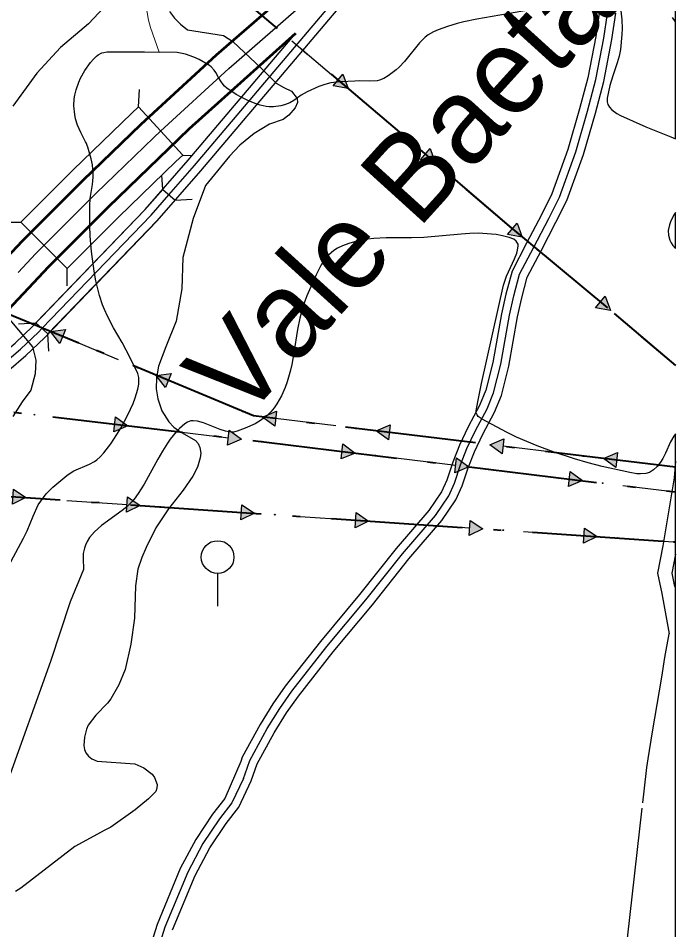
# Model space of a CAD drawing. Extents: x -64005 to -55000, y -89025 to -80000.
# Drawn here: x -55804 to -55000, y -84948 to -83834 of the extents above; entities that cross this region are included whole.
import ezdxf
from ezdxf.enums import TextEntityAlignment as Align

# ---------------------------------------------------------------- set-up
doc = ezdxf.new("R2010")
doc.units = 0
doc.header["$LTSCALE"] = 32
for name, pattern in [('DASH_DOUBLE_DOT', [9.2, 5, -1.2, 0.3, -1.2, 0.3, -1.2]), ('DOT_DASHED', [7.7, 5, -1.2, 0.3, -1.2]), ('LONG_DASHED', [7.5, 6, -1.5])]:
    doc.linetypes.add(name, pattern=pattern)
for name, color, linetype, lineweight in [('1', 7, 'Continuous', 25), ('18', 7, 'Continuous', 25), ('2', 7, 'Continuous', 25), ('20', 7, 'Continuous', 25), ('24', 7, 'Continuous', 25), ('32', 7, 'Continuous', 25), ('39', 7, 'LONG_DASHED', 25), ('53', 7, 'DASH_DOUBLE_DOT', 25), ('6', 7, 'Continuous', 25), ('63', 7, 'DASH_DOUBLE_DOT', 25), ('8', 7, 'Continuous', 25)]:
    doc.layers.add(name, color=color, linetype=linetype, lineweight=lineweight)
doc.layers.add('46', color=7, linetype='Continuous')

msp = doc.modelspace()

# ---------------------------------------------------------------- hatches: boundary and pattern name
at = {"layer": '18'}
for points in [[(-55407.16, -83902.59), (-55400.91, -83920), (-55419.11, -83916.71)], [(-55300.36, -83993.23), (-55294.25, -84010.69), (-55312.43, -84007.25)], [(-55194.27, -84084.32), (-55187.85, -84101.66), (-55206.08, -84098.56)], [(-55086.52, -84173.7), (-55080.1, -84191.05), (-55098.34, -84187.94)], [(-55753.42, -84231.68), (-55764.71, -84217.02), (-55746.38, -84214.57)], [(-55624.16, -84285.36), (-55635.4, -84270.67), (-55617.05, -84268.28)], [(-55685.16, -84321.01), (-55670.34, -84332.09), (-55687.34, -84339.38)], [(-55490.56, -84332.57), (-55505.35, -84321.45), (-55488.33, -84314.2)], [(-55351.58, -84349.45), (-55366.37, -84338.34), (-55349.35, -84331.09)], [(-55546.14, -84337.53), (-55531.32, -84348.61), (-55548.32, -84355.9)], [(-55407.12, -84354.29), (-55392.33, -84365.41), (-55409.35, -84372.66)], [(-55212.61, -84366.34), (-55227.39, -84355.23), (-55210.37, -84347.97)], [(-55073.63, -84383.23), (-55088.42, -84372.11), (-55071.4, -84364.86)], [(-55268.14, -84371.18), (-55253.35, -84382.29), (-55270.37, -84389.54)], [(-55129.16, -84388.06), (-55114.38, -84399.18), (-55131.4, -84406.43)], [(-55810.13, -84409.61), (-55794.78, -84419.93), (-55811.39, -84428.07)], [(-55670.45, -84419.14), (-55655.1, -84429.46), (-55671.71, -84437.59)], [(-55530.78, -84428.66), (-55515.43, -84438.98), (-55532.04, -84447.12)], [(-55391.1, -84438.18), (-55375.75, -84448.5), (-55392.36, -84456.64)], [(-55251.43, -84447.71), (-55236.07, -84458.03), (-55252.69, -84466.17)], [(-55111.75, -84457.23), (-55096.4, -84467.55), (-55113.01, -84475.69)]]:
    msp.add_hatch(color=256, dxfattribs=at).paths.add_polyline_path(points)

# ---------------------------------------------------------------- linework, layer by layer
at = {"layer": '1'}
for points in [[(-55699.54, -83821.02), (-55718.23, -83840.76), (-55752.5, -83869.85), (-55781.57, -83901.01), (-55810.64, -83941.52)], [(-55619.26, -83825.9), (-55613.16, -83834.17), (-55606.01, -83841.41), (-55597.05, -83848.28), (-55553.13, -83855.3), (-55541.71, -83862.57), (-55506.76, -83895.65), (-55488.75, -83913.47), (-55479.53, -83918.8), (-55470, -83923.27), (-55463.17, -83931.97), (-55462.86, -83937.07), (-55465.74, -83943.58), (-55473.31, -83952.36), (-55480.07, -83957.94)], [(-55480.07, -83957.94), (-55497.06, -83963.34), (-55515.75, -83974.76), (-55533.4, -83989.3), (-55545.86, -84002.81), (-55575.04, -84038.43), (-55590.51, -84078.64), (-55602.97, -84126.42), (-55604.01, -84164.86), (-55611.28, -84204.33)], [(-55821.03, -84194.98), (-55786.76, -84235.49), (-55782.61, -84252.11), (-55783.65, -84268.73), (-55788.84, -84288.47), (-55799.22, -84303.01), (-55810.64, -84320.67)], [(-55611.28, -84204.33), (-55623.86, -84235.72), (-55632.51, -84259.11), (-55635.19, -84273.58), (-55635.43, -84287.06), (-55633.65, -84299.04), (-55628.46, -84313.91), (-55619.93, -84327.36), (-55613.89, -84333.65), (-55606.8, -84339.06), (-55587.51, -84350.27), (-55584.38, -84353.91), (-55582.14, -84358.55), (-55581.11, -84365.39), (-55581.9, -84371.12), (-55585.2, -84382.58), (-55590.75, -84393.57), (-55602.48, -84410.82), (-55620.32, -84433.74), (-55635.86, -84456.9), (-55647.94, -84480.83), (-55653.2, -84493.27), (-55657.82, -84507.31), (-55660.75, -84527.59), (-55662.08, -84567.03), (-55666.48, -84598.8), (-55673.67, -84630.02), (-55681.21, -84648.67), (-55690.9, -84665.61), (-55695.09, -84670.94), (-55709.37, -84685.63), (-55718.64, -84698.06), (-55720.7, -84702.85)], [(-55720.7, -84702.85), (-55723.08, -84712.8), (-55723.9, -84722.71), (-55723.08, -84727.65), (-55721.43, -84731.69), (-55718.15, -84736.04), (-55714.08, -84739.12), (-55707.66, -84741.93), (-55661.68, -84745.11), (-55650.66, -84750.11), (-55640.56, -84757.81), (-55637.44, -84761.79), (-55634.52, -84770.37), (-55634.57, -84774.94), (-55635.93, -84779.01), (-55644.83, -84788.16), (-55661.42, -84801.55), (-55691.01, -84822.41), (-55698.21, -84826.25), (-55735.19, -84846.34), (-55801.11, -84896.96), (-55807.58, -84901.34)]]:
    msp.add_lwpolyline(points, dxfattribs=at)
at = {"layer": '18'}
for p, q in [((-55469.61, -83861.86), (-55413.14, -83909.65)), ((-55149.37, -84133.59), (-55092.43, -84180.82)), ((-55041.91, -84223.32), (-55000.5, -84258.41)), ((-55552.3, -84305.23), (-55620.61, -84276.82)), ((-55759.71, -84321.47), (-55686.25, -84330.2)), ((-55416.01, -84332.31), (-55489.45, -84323.38)), ((-55620.69, -84337.99), (-55547.23, -84346.72)), ((-55277.03, -84349.19), (-55350.47, -84340.27)), ((-55481.68, -84354.55), (-55408.24, -84363.48)), ((-55138.05, -84366.08), (-55211.49, -84357.16)), ((-55342.7, -84371.44), (-55269.26, -84380.36)), ((-55000.49, -84382.8), (-55072.51, -84374.04)), ((-55203.72, -84388.32), (-55130.28, -84397.25)), ((-55064.74, -84405.21), (-55000.48, -84413.02)), ((-55744.89, -84423.33), (-55671.08, -84428.37)), ((-55605.22, -84432.86), (-55531.41, -84437.89)), ((-55465.54, -84442.38), (-55391.73, -84447.41)), ((-55325.87, -84451.9), (-55252.06, -84456.94)), ((-55186.19, -84461.43), (-55112.38, -84466.46))]:
    msp.add_line(p, q, dxfattribs=at)
at = {"layer": '18', "linetype": 'DOT_DASHED', "lineweight": 40}
for points in [[(-55896.2, -83499.07), (-55797.62, -83584.26), (-55324.44, -83984.71), (-55206.84, -84085.91), (-55075.34, -84195), (-55000.54, -84258.38)], [(-55000.53, -84382.79), (-55516.56, -84320.09), (-55729.93, -84231.35), (-55898.21, -84162.02), (-56153.65, -84175.49), (-56582.99, -84192.51), (-56626.76, -84187.31), (-57504.59, -84083.05), (-58001.88, -84024.51), (-58160.87, -84004.69), (-58191.9, -84001.28), (-58270.88, -83992.6), (-59155.35, -83888.5), (-59176.97, -83888)], [(-59157.46, -83918.46), (-58274.27, -84022.41), (-58164.58, -84034.46), (-58005.49, -84054.29), (-57508.11, -84112.84), (-56655.47, -84214.11), (-56569.95, -84224.07), (-56422.5, -84248.65), (-56353.68, -84279.25), (-56260.52, -84304.64), (-56178.14, -84312.38), (-56096.81, -84306.21), (-56006.78, -84292.12), (-55500.64, -84352.25), (-55000.53, -84413.01)], [(-59208.4, -83960.92), (-58840.52, -84105.61), (-58451.92, -84258.45), (-57960.33, -84286.53), (-57618.65, -84306.04), (-56803.81, -84352.58), (-56672.75, -84360.07), (-56310.07, -84384.67), (-56232.21, -84401.36), (-56177.98, -84406.92), (-56111.94, -84406.23), (-55912.72, -84411.89), (-55002.84, -84473.93), (-55000.52, -84474.09)]]:
    msp.add_lwpolyline(points, dxfattribs=at)
at = {"layer": '18'}
for points in [[(-55407.16, -83902.59), (-55400.91, -83920), (-55419.11, -83916.71)], [(-55300.36, -83993.23), (-55294.25, -84010.69), (-55312.43, -84007.25)], [(-55194.27, -84084.32), (-55187.85, -84101.66), (-55206.08, -84098.56)], [(-55086.52, -84173.7), (-55080.1, -84191.05), (-55098.34, -84187.94)], [(-55753.42, -84231.68), (-55764.71, -84217.02), (-55746.38, -84214.57)], [(-55624.16, -84285.36), (-55635.4, -84270.67), (-55617.05, -84268.28)], [(-55685.16, -84321.01), (-55670.34, -84332.09), (-55687.34, -84339.38)], [(-55490.56, -84332.57), (-55505.35, -84321.45), (-55488.33, -84314.2)], [(-55351.58, -84349.45), (-55366.37, -84338.34), (-55349.35, -84331.09)], [(-55546.14, -84337.53), (-55531.32, -84348.61), (-55548.32, -84355.9)], [(-55407.12, -84354.29), (-55392.33, -84365.41), (-55409.35, -84372.66)], [(-55212.61, -84366.34), (-55227.39, -84355.23), (-55210.37, -84347.97)], [(-55073.63, -84383.23), (-55088.42, -84372.11), (-55071.4, -84364.86)], [(-55268.14, -84371.18), (-55253.35, -84382.29), (-55270.37, -84389.54)], [(-55129.16, -84388.06), (-55114.38, -84399.18), (-55131.4, -84406.43)], [(-55810.13, -84409.61), (-55794.78, -84419.93), (-55811.39, -84428.07)], [(-55670.45, -84419.14), (-55655.1, -84429.46), (-55671.71, -84437.59)], [(-55530.78, -84428.66), (-55515.43, -84438.98), (-55532.04, -84447.12)], [(-55391.1, -84438.18), (-55375.75, -84448.5), (-55392.36, -84456.64)], [(-55251.43, -84447.71), (-55236.07, -84458.03), (-55252.69, -84466.17)], [(-55111.75, -84457.23), (-55096.4, -84467.55), (-55113.01, -84475.69)]]:
    msp.add_lwpolyline(points, close=True, dxfattribs=at)
for points in [[(-55362.74, -83952.3), (-55324.44, -83984.71), (-55306.4, -84000.24)], [(-55256.36, -84043.3), (-55206.84, -84085.91), (-55200.18, -84091.44)], [(-55681.56, -84251.47), (-55729.93, -84231.35), (-55749.9, -84223.12)], [(-55046.51, -84470.95), (-55002.84, -84473.93), (-55000.48, -84474.09)]]:
    msp.add_lwpolyline(points, dxfattribs=at)
for centre in [(-55488.69, -83845.7), (-55381.82, -83936.14), (-55275.31, -84026.99), (-55168.61, -84117.62), (-55787.83, -84207.5), (-55060.98, -84207.16), (-55658.48, -84261.07), (-55784.54, -84318.52), (-55529.21, -84314.83), (-55645.52, -84335.04), (-55391.19, -84335.32), (-55506.5, -84351.55), (-55252.21, -84352.21), (-55367.52, -84368.42), (-55113.23, -84369.1), (-55228.54, -84385.31), (-55089.56, -84402.19), (-55769.84, -84421.63), (-55630.16, -84431.15), (-55490.48, -84440.68), (-55350.81, -84450.2), (-55211.13, -84459.73), (-55071.46, -84469.25)]:
    msp.add_circle(centre, 0.5, dxfattribs=at)
at = {"layer": '2', "lineweight": 53}
for points in [[(-55818.31, -84126.55), (-55799, -84106.08), (-55725.3, -84032.32), (-55653.89, -83963.36), (-55561.91, -83878.94), (-55466.51, -83795.7), (-55339.87, -83690.16), (-55239.53, -83612.08), (-55178.74, -83566.18), (-55119.64, -83523.93)], [(-55912.73, -84293.46), (-55891.29, -84269.48), (-55766.72, -84137.44), (-55693.76, -84064.42), (-55595.28, -83969.31), (-55464.59, -83852.14)]]:
    msp.add_lwpolyline(points, dxfattribs=at)
at = {"layer": '2'}
for points in [[(-55630.21, -83972.16), (-55546.9, -83895.71), (-55451.91, -83812.82), (-55337, -83717.05)], [(-55177.66, -83823.77), (-55243.3, -83835.37), (-55259.4, -83838.68), (-55267.38, -83840.63), (-55279.2, -83844.09), (-55290.83, -83848.37), (-55296.56, -83850.89), (-55302.82, -83854.49), (-55306.6, -83857.38), (-55313.42, -83864.05), (-55331.75, -83886.93), (-55338.52, -83893.92), (-55342.27, -83897.03), (-55351.92, -83904.55), (-55357, -83907.75), (-55362.44, -83909.92), (-55365.33, -83910.46), (-55374.41, -83910.92), (-55386.54, -83910.77), (-55392.59, -83910.88), (-55409.66, -83911.77), (-55418.18, -83912.56), (-55421.98, -83913.14), (-55429.43, -83915.01), (-55436.69, -83917.59), (-55450.89, -83923.89), (-55458.09, -83928.15), (-55467.26, -83934.56), (-55472.28, -83937.31), (-55478.76, -83939.81), (-55483.14, -83941.01), (-55491.99, -83942.35), (-55497.43, -83942.35), (-55501.08, -83941.93), (-55508.35, -83940.25), (-55513.27, -83938.65), (-55522.75, -83934.92), (-55531.81, -83930.5), (-55537.66, -83927.18), (-55549.02, -83919.71), (-55551.96, -83917.15), (-55553.65, -83915.21), (-55556.57, -83910.92), (-55559.16, -83906.32), (-55562.67, -83900.22), (-55564.68, -83897.38), (-55568.26, -83893.61), (-55570.41, -83892.03), (-55583.12, -83884.69), (-55589.66, -83881.63), (-55599.69, -83878.08), (-55610.01, -83876.03), (-55632.06, -83875.48)], [(-55000.58, -83838.4), (-55004.09, -83833.21)], [(-55721.34, -83986.37), (-55721.78, -83985.29), (-55727.82, -83973.66), (-55731.88, -83964.6), (-55734.16, -83956.84), (-55735.19, -83951.59), (-55736.07, -83941.12), (-55735.64, -83932.43), (-55735.01, -83928.12), (-55733.57, -83921.7), (-55730.25, -83912.14), (-55728.07, -83907.39), (-55722.65, -83897.91), (-55716.01, -83888.33), (-55712.38, -83884.03), (-55708.47, -83880.36), (-55706.39, -83878.82), (-55701.95, -83876.5), (-55699.58, -83875.76), (-55695.81, -83875.27), (-55649.67, -83875.26), (-55632.06, -83875.48)], [(-55772.81, -84111.7), (-55709.53, -84048.37), (-55638.47, -83979.74), (-55630.21, -83972.16)], [(-55716.78, -84063.16), (-55716.12, -84054.48), (-55713.53, -84037.15), (-55712.67, -84028.49), (-55712.58, -84024.16), (-55713.59, -84013.16), (-55715.06, -84005.88), (-55719.29, -83991.44), (-55721.34, -83986.37)], [(-55825.39, -84521.14), (-55797.71, -84469.57), (-55793.49, -84460.66), (-55786.02, -84442.38), (-55779.68, -84428.88), (-55776.78, -84424.08), (-55769.95, -84415.28), (-55762.08, -84407.33), (-55744.87, -84392.81), (-55742.1, -84390.75), (-55736.14, -84387.28), (-55716.97, -84378.89), (-55710.93, -84375.57), (-55708.1, -84373.6), (-55704.18, -84370.15), (-55699.46, -84365.02), (-55690.98, -84354.25), (-55683.5, -84342.85), (-55678.91, -84334.96), (-55670.22, -84318.56), (-55663.89, -84304.96), (-55661.24, -84298.07), (-55658.05, -84287.53), (-55656.91, -84281.19), (-55656.69, -84277.92), (-55656.93, -84273.04), (-55658, -84268.36), (-55658.89, -84266.14), (-55672.32, -84239.72), (-55677.34, -84230.51), (-55687.57, -84212.23), (-55694.97, -84198.21), (-55698.79, -84189.88), (-55701.03, -84184.22), (-55704.86, -84172.71), (-55709.23, -84155.04), (-55711.42, -84143.07), (-55714.68, -84118.94), (-55716.26, -84100.35), (-55716.76, -84087.93), (-55716.78, -84063.16)], [(-55804.44, -84144.64), (-55782.86, -84121.76), (-55772.81, -84111.7)]]:
    msp.add_lwpolyline(points, dxfattribs=at)
at = {"layer": '2', "lineweight": 13}
msp.add_lwpolyline([(-55632.06, -83875.48), (-55642.55, -83845.38), (-55644.95, -83836.59), (-55651.77, -83796.31)], dxfattribs=at)
at = {"layer": '20'}
for points in [[(-55822.36, -84083.48), (-55801.15, -84083.47), (-55737.32, -84019.6), (-55665.51, -83950.27), (-55657.04, -83942.49), (-55656.13, -83921.3)], [(-55744.55, -84161.23), (-55744.55, -84140.02), (-55681.74, -84077.14), (-55611.43, -84009.21), (-55602.95, -84001.43), (-55591.54, -84001.92)], [(-55804.05, -84207.56), (-55782.86, -84206.51), (-55649.3, -84068.27), (-55627.6, -84043.4), (-55628.78, -84025.98)], [(-55766.99, -84241.12), (-55768.04, -84219.93), (-55634.24, -84081.43), (-55612.53, -84056.55), (-55591.36, -84055.11)]]:
    msp.add_lwpolyline(points, dxfattribs=at)
at = {"layer": '24'}
msp.add_line((-55000.18, -87240.01), (-55000.49, -84341.86), dxfattribs=at)
for points in [[(-55081.28, -83942.82), (-55078.41, -83945.85), (-55072.27, -83950.57), (-55067.95, -83952.99), (-55036.91, -83966.82), (-55006.07, -83978.86), (-55000.52, -83981.34), (-55000.56, -83658.31)], [(-55067.31, -83825.18), (-55066.13, -83835.94), (-55065.9, -83846.82), (-55066.15, -83854.07), (-55067.77, -83872.48), (-55069.47, -83880.54), (-55071.81, -83888.54), (-55077.29, -83904.42), (-55080.97, -83916.34), (-55084.09, -83931.62), (-55084.09, -83936.31), (-55083.35, -83939.31), (-55081.28, -83942.82)], [(-55000.52, -84071.37), (-55002.29, -84074.1), (-55006.3, -84081.83), (-55007.99, -84086.46), (-55009.29, -84093.41), (-55009.02, -84099.18), (-55007.38, -84105.48)], [(-55007.38, -84105.48), (-55005.92, -84108.59), (-55003.85, -84111.68), (-55000.51, -84115.27), (-55000.52, -84071.37)], [(-55195.32, -84106.57), (-55198.31, -84104.25), (-55203.98, -84102.16), (-55211.98, -84100.01), (-55219.99, -84098.49), (-55225.33, -84097.78), (-55241.37, -84096.91), (-55252.07, -84097.15), (-55262.76, -84097.86), (-55308.15, -84102.04), (-55323.51, -84102.44), (-55354.22, -84102.46), (-55369.55, -84103.26), (-55377.2, -84104.12), (-55387.37, -84105.89), (-55400.07, -84109.37), (-55407.66, -84112.26), (-55413.85, -84115.18), (-55418.28, -84117.97), (-55424.65, -84123.48), (-55428.99, -84128.56), (-55433.64, -84135.58), (-55439.85, -84147.82), (-55451.14, -84173.2), (-55453.88, -84179.88), (-55456.22, -84186.66), (-55459.92, -84200.47), (-55462.67, -84214.54), (-55467.12, -84243.03), (-55469.69, -84257.26), (-55471.25, -84264.32), (-55475.22, -84278.29), (-55477.73, -84285.17), (-55482.31, -84295.32), (-55488.04, -84305.23), (-55491.39, -84310.09), (-55495.44, -84315.04), (-55500.34, -84319.85), (-55504.54, -84323.23), (-55507.81, -84325.53), (-55514.65, -84329.57), (-55526.61, -84335.06), (-55536.38, -84338.74), (-55540.94, -84339.75), (-55546.23, -84339.68), (-55550.59, -84338.88), (-55557.29, -84336.79), (-55577.53, -84328.48), (-55585.07, -84326.39), (-55590.2, -84325.95), (-55593.16, -84326.24), (-55597.38, -84327.6), (-55600.68, -84329.71), (-55607.12, -84335.5), (-55611.09, -84339.65), (-55618.33, -84348.55), (-55621.66, -84353.24), (-55627.86, -84363), (-55633.6, -84373.09), (-55650.06, -84403.36), (-55657.51, -84415.07), (-55662.38, -84421.59), (-55664.97, -84424.68), (-55671.38, -84431.06), (-55677.18, -84435.82), (-55702.33, -84454.15), (-55710.9, -84461.74), (-55716.95, -84468.81), (-55719.95, -84473.47), (-55722.06, -84477.81), (-55723.38, -84481.67), (-55724.65, -84488.38), (-55724.94, -84493.94), (-55724.43, -84507.57)], [(-55000.49, -84341.86), (-55002.73, -84344.99), (-55006.51, -84351.65), (-55012.74, -84365.5), (-55016.14, -84372.29), (-55018.82, -84376.65), (-55022.88, -84381.79), (-55027.43, -84386.04), (-55032.42, -84389.02), (-55036.7, -84390.35), (-55043.36, -84390.97), (-55047.85, -84390.7), (-55056.54, -84389.27), (-55090.37, -84381.74), (-55107.2, -84377.41), (-55123.98, -84372.63), (-55149.05, -84364.48), (-55169.88, -84356.67), (-55194.8, -84345.88), (-55207.24, -84339.86), (-55237.12, -84324.09), (-55241.77, -84320.58), (-55243.2, -84318.79), (-55244.2, -84316.31), (-55244.2, -84313.8), (-55242.13, -84302.67), (-55237.59, -84280.38), (-55210.75, -84160.13), (-55209.79, -84156.46), (-55207.17, -84149.22), (-55197.33, -84128.06), (-55194.7, -84121.08), (-55193.72, -84117.59), (-55192.82, -84112.34), (-55193.02, -84110.36), (-55193.68, -84108.78), (-55195.32, -84106.57)], [(-55724.43, -84507.57), (-55740.54, -84547.07), (-55764.89, -84620.17), (-55818.15, -84769.41), (-55872.72, -84864.67)]]:
    msp.add_lwpolyline(points, dxfattribs=at)
at = {"layer": '32'}
msp.add_line((-55560.39, -84512.53), (-55560.39, -84552.53), dxfattribs=at)
msp.add_circle((-55560.39, -84492.53), 20, dxfattribs=at)
at = {"layer": '39', "linetype": 'Continuous'}
for points in [[(-55620.06, -84049.97), (-55588.66, -84013.99), (-55337, -83717.05)], [(-55775.45, -84213.21), (-55641.77, -84074.85), (-55620.06, -84049.97)], [(-55885.12, -84303.09), (-55876.69, -84298.01), (-55843.25, -84274.06), (-55801.45, -84238.69), (-55779.41, -84217.59), (-55775.45, -84213.21)]]:
    msp.add_lwpolyline(points, dxfattribs=at)
at = {"layer": '39'}
for points in [[(-55528.81, -84763.1), (-55526.85, -84757.57), (-55521.11, -84741.33), (-55499.72, -84702.17), (-55484.49, -84677.51), (-55469.63, -84656.48), (-55426.84, -84601.97), (-55378.99, -84544.67), (-55334.4, -84488.47), (-55294.15, -84441.69), (-55277.85, -84417.76), (-55270.85, -84402.05), (-55263.6, -84379.93), (-55255.63, -84359.99), (-55245.11, -84337.87), (-55230.97, -84311.39), (-55223, -84291.81), (-55214.3, -84257), (-55203.42, -84197.06), (-55198.34, -84173.49), (-55191.09, -84146.66), (-55173.69, -84113.66), (-55155.56, -84078.84), (-55142.51, -84052.74), (-55122.57, -83997.51), (-55108.07, -83947.47), (-55097.92, -83909.04), (-55088.13, -83858.26), (-55083.79, -83828.17)], [(-55528.81, -84763.1), (-55542.9, -84792.75), (-55558.22, -84812.49), (-55578.55, -84842.64), (-55596.99, -84877.41), (-55625.04, -84944.84), (-55637.18, -84983.8)]]:
    msp.add_lwpolyline(points, dxfattribs=at)
at = {"layer": '53'}
for points in [[(-55000.53, -84375.18), (-55002.16, -84395.52), (-55015.85, -84479.01), (-55022.39, -84512.29), (-55017.2, -84537.22), (-55008.43, -84586.18)], [(-55059.02, -84958.32), (-55040.48, -84793), (-55038.65, -84778.49), (-55035.38, -84749.79), (-55034.11, -84738.97), (-55028.58, -84706.1), (-55023, -84672.79), (-55017.37, -84639.4), (-55013.39, -84615.27), (-55008.43, -84586.18)]]:
    msp.add_lwpolyline(points, dxfattribs=at)
at = {"layer": '6'}
for points in [[(-56401.93, -84330), (-56363.68, -84348.53), (-56324.24, -84362.84), (-56284.31, -84374.6), (-56242.62, -84383.09), (-56203.39, -84388.41), (-56167.14, -84390.15), (-56133.35, -84389.18), (-56094.64, -84386.28), (-56051, -84379.52), (-56024.28, -84373.03), (-55999.13, -84366.06), (-55950.75, -84348.71), (-55907.3, -84328.13), (-55871.19, -84306.37), (-55837.1, -84281.95), (-55794.76, -84246.13), (-55772.24, -84224.57), (-55634.47, -84081.7), (-55581.08, -84020.51), (-55376.88, -83779.58)], [(-56425.37, -84292.98), (-56397.09, -84310.13), (-56355.9, -84330.09), (-56318, -84343.82), (-56279.47, -84355.18), (-56239.28, -84363.37), (-56201.57, -84368.47), (-56166.94, -84370.13), (-56134.39, -84369.2), (-56096.92, -84366.4), (-56054.9, -84359.88), (-56029.32, -84353.67), (-56005.19, -84346.98), (-55958.43, -84330.21), (-55916.76, -84310.49), (-55882.19, -84289.65), (-55849.4, -84266.17), (-55808.14, -84231.25), (-55786.58, -84210.61), (-55649.07, -84068), (-55596.24, -84007.47), (-55464.59, -83852.14)]]:
    msp.add_lwpolyline(points, dxfattribs=at)
at = {"layer": '63'}
for points in [[(-55801.15, -84083.47), (-55737.32, -84019.6), (-55665.51, -83950.27), (-55657.04, -83942.49), (-55602.95, -84001.43), (-55611.43, -84009.21), (-55681.74, -84077.14), (-55744.55, -84140.02)], [(-55782.86, -84206.51), (-55649.3, -84068.27), (-55627.6, -84043.4), (-55612.53, -84056.55), (-55634.24, -84081.43), (-55768.04, -84219.93)]]:
    msp.add_lwpolyline(points, close=True, dxfattribs=at)
at = {"layer": '8'}
msp.add_line((-55001.01, -84529.04), (-55000.52, -84529.5), dxfattribs=at)
at = {"layer": '8', "linetype": 'LONG_DASHED'}
for points in [[(-55093.94, -83828.07), (-55097.99, -83856.6), (-55107.68, -83906.81), (-55117.71, -83944.8), (-55132.09, -83994.43), (-55151.72, -84048.79), (-55164.47, -84074.29), (-55182.55, -84109.02), (-55200.45, -84142.98), (-55208.07, -84171.13), (-55213.23, -84195.12), (-55224.08, -84254.89), (-55232.53, -84288.7), (-55240.04, -84307.14), (-55254.04, -84333.36), (-55264.8, -84355.98), (-55273, -84376.51), (-55280.19, -84398.45), (-55286.62, -84412.87), (-55302.1, -84435.59), (-55342.11, -84482.1), (-55386.75, -84538.36), (-55434.61, -84595.68), (-55477.65, -84650.5), (-55492.83, -84671.99), (-55508.37, -84697.14), (-55530.27, -84737.24), (-55532.11, -84742.44)], [(-55000.52, -84489.14), (-55005.05, -84512.19), (-55001.67, -84528.43), (-55001.01, -84529.04)], [(-55532.11, -84742.44), (-55551.47, -84787.48), (-55566.51, -84806.9), (-55587.14, -84837.49), (-55606.04, -84873.14), (-55634.45, -84941.43), (-55646.7, -84980.75)]]:
    msp.add_lwpolyline(points, dxfattribs=at)
at = {"layer": '8'}
for points in [[(-55519.22, -84765.98), (-55511.95, -84745.42), (-55491.07, -84707.2), (-55476.15, -84683.03), (-55461.61, -84662.46), (-55419.07, -84608.26), (-55371.23, -84550.98), (-55326.69, -84494.84), (-55286.2, -84447.79), (-55269.08, -84422.64), (-55261.51, -84405.65), (-55254.2, -84383.35), (-55246.46, -84364), (-55236.18, -84342.38), (-55221.9, -84315.64), (-55213.47, -84294.92), (-55204.52, -84259.11), (-55193.6, -84199.01), (-55188.62, -84175.85), (-55181.73, -84150.34), (-55164.83, -84118.3), (-55146.65, -84083.39), (-55133.3, -84056.69), (-55113.05, -84000.6), (-55098.43, -83950.14), (-55088.16, -83911.27), (-55078.27, -83859.92), (-55073.67, -83828.03)], [(-55615.63, -84948.26), (-55587.94, -84881.68), (-55569.96, -84847.79), (-55549.93, -84818.08), (-55534.33, -84798.02), (-55519.22, -84765.98)]]:
    msp.add_lwpolyline(points, dxfattribs=at)

# ---------------------------------------------------------------- texts
at = {"layer": '46'}
msp.add_text('Vale Baeta', height=105, rotation=47.802, dxfattribs=at).set_placement((-55299.78, -84075.45), align=Align.CENTER)

doc.saveas('drawing.dxf')
